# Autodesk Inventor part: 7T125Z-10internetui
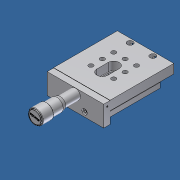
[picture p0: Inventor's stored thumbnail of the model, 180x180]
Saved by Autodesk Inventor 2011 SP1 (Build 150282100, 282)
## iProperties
Created: 2011-05
Part Number: 7T125Z-10internetui
Document SubType Name: Modeling
Designer: Darius
Density: 1 g/cm^3
Author: Darius
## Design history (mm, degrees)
feature "Base1"
body "Solid1"
